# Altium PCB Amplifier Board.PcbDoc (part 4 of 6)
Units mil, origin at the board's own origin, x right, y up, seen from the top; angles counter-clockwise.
Board outline 6000 x 2640 mil, 6 copper layers (Top Layer, GND, VCC, BASES, GND (Plane3), Bottom Layer), stack 63.9 mil thick; 884 components, 484 nets, 2029 pads, 464 vias.
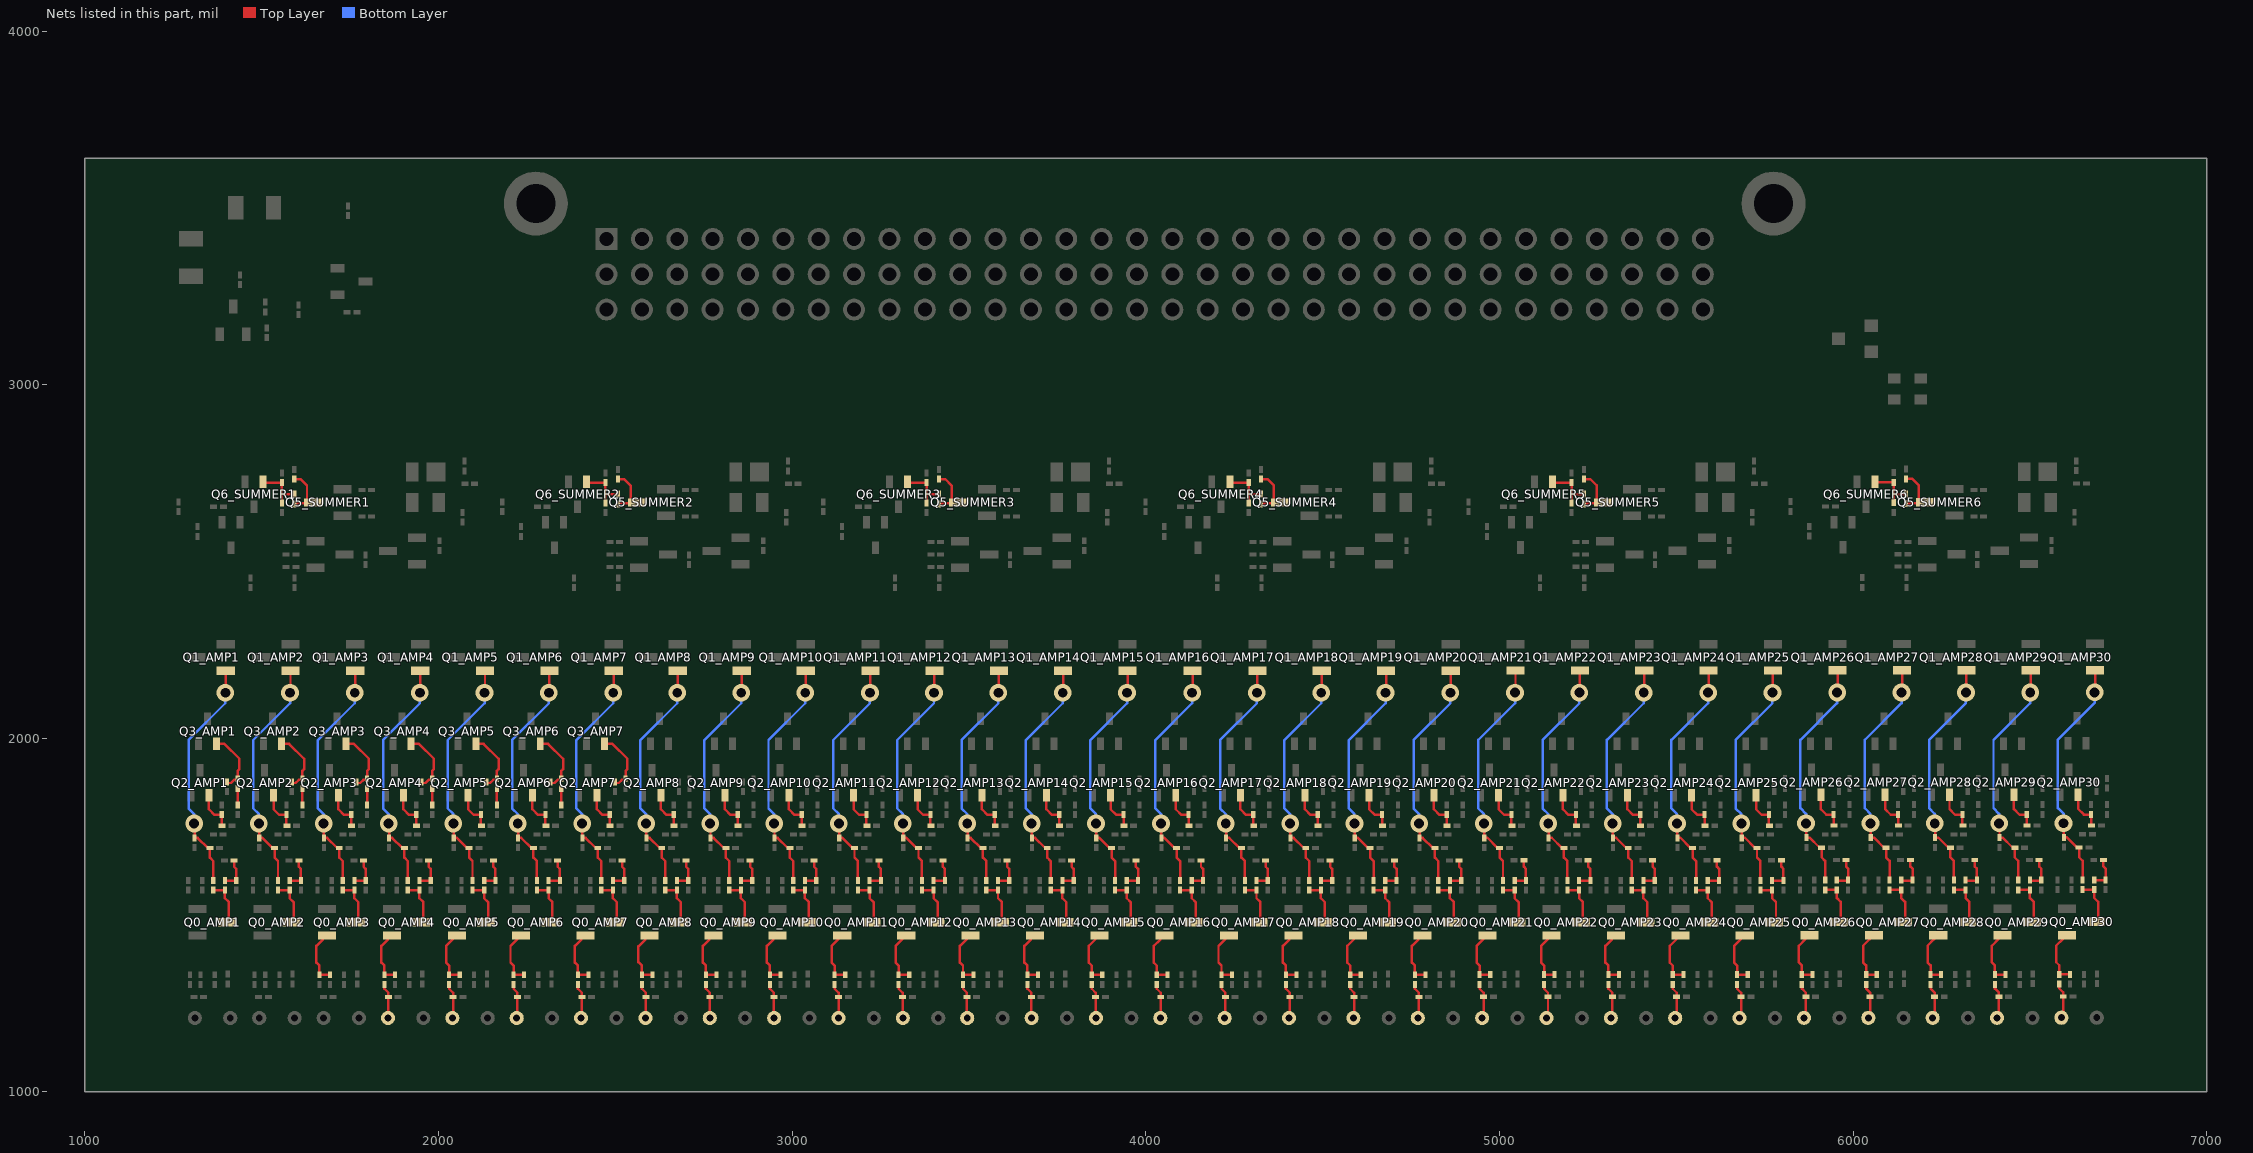
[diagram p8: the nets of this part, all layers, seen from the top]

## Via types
v1: diameter 50, hole 28, Top Layer to Bottom Layer, 433 vias
v2: diameter 50, hole 28, Top Layer to Bottom Layer, tented top, 31 vias

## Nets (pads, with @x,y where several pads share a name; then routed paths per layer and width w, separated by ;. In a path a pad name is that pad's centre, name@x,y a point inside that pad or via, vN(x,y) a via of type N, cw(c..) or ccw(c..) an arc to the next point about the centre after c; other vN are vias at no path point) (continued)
NetC2_AMP3_2: C2_AMP3.2 Q0_AMP3.2 R1_AMP3.2 | length 152.2
  Top Layer w7: Q0_AMP3.2@1673,1442.6 1673,1431.56 1654.5,1413.06 1654.5,1365.93 1663,1357.43 C2_AMP3.2@1663,1331.56 R1_AMP3.2@1693,1331.56
NetC2_AMP4_1: C2_AMP4.1 R19_AMP4.2 SIPM_AMP4.1 | length 98.4
  Top Layer w7: C2_AMP4.1@1847,1304 1847,1291.88 1858.22,1280.66 R19_AMP4.2@1858.22,1269 SIPM_AMP4.1@1858.22,1210.22
NetC2_AMP4_2: C2_AMP4.2 Q0_AMP4.2 R1_AMP4.2 | length 152.2
  Top Layer w7: Q0_AMP4.2@1857,1442.6 1857,1431.56 1838.5,1413.06 1838.5,1365.93 1847,1357.43 C2_AMP4.2@1847,1331.56 R1_AMP4.2@1877,1331.56
NetC2_AMP5_1: C2_AMP5.1 R19_AMP5.2 SIPM_AMP5.1 | length 98.4
  Top Layer w7: C2_AMP5.1@2030,1304 2030,1291.88 2041.22,1280.66 R19_AMP5.2@2041.22,1269 SIPM_AMP5.1@2041.22,1210.22
NetC2_AMP5_2: C2_AMP5.2 Q0_AMP5.2 R1_AMP5.2 | length 152.2
  Top Layer w7: Q0_AMP5.2@2040,1442.6 2040,1431.56 2021.5,1413.06 2021.5,1365.93 2030,1357.43 C2_AMP5.2@2030,1331.56 R1_AMP5.2@2060,1331.56
NetC2_AMP6_1: C2_AMP6.1 R19_AMP6.2 SIPM_AMP6.1 | length 98.4
  Top Layer w7: C2_AMP6.1@2212,1304 2212,1291.88 2223.22,1280.66 R19_AMP6.2@2223.22,1269 SIPM_AMP6.1@2223.22,1210.22
NetC2_AMP6_2: C2_AMP6.2 Q0_AMP6.2 R1_AMP6.2 | length 152.2
  Top Layer w7: Q0_AMP6.2@2222,1442.6 2222,1431.56 2203.5,1413.06 2203.5,1365.93 2212,1357.43 C2_AMP6.2@2212,1331.56 R1_AMP6.2@2242,1331.56
NetC2_AMP7_1: C2_AMP7.1 R19_AMP7.2 SIPM_AMP7.1 | length 98.4
  Top Layer w7: C2_AMP7.1@2394,1304 2394,1291.88 2405.22,1280.66 R19_AMP7.2@2405.22,1269 SIPM_AMP7.1@2405.22,1210.22
NetC2_AMP7_2: C2_AMP7.2 Q0_AMP7.2 R1_AMP7.2 | length 152.2
  Top Layer w7: Q0_AMP7.2@2404,1442.6 2404,1431.56 2385.5,1413.06 2385.5,1365.93 2394,1357.43 C2_AMP7.2@2394,1331.56 R1_AMP7.2@2424,1331.56
NetC2_AMP8_1: C2_AMP8.1 R19_AMP8.2 SIPM_AMP8.1 | length 98.4
  Top Layer w7: C2_AMP8.1@2575,1304 2575,1291.88 2586.22,1280.66 R19_AMP8.2@2586.22,1269 SIPM_AMP8.1@2586.22,1210.22
NetC2_AMP8_2: C2_AMP8.2 Q0_AMP8.2 R1_AMP8.2 | length 153.5
  Top Layer w7: Q0_AMP8.2@2585,1442.6 2585,1431.56 2565,1411.56 2565,1367.43 2575,1357.43 C2_AMP8.2@2575,1331.56 R1_AMP8.2@2605,1331.56
NetC2_AMP9_1: C2_AMP9.1 R19_AMP9.2 SIPM_AMP9.1 | length 98.4
  Top Layer w7: C2_AMP9.1@2756,1304 2756,1291.88 2767.22,1280.66 R19_AMP9.2@2767.22,1269 SIPM_AMP9.1@2767.22,1210.22
NetC2_AMP9_2: C2_AMP9.2 Q0_AMP9.2 R1_AMP9.2 | length 152.2
  Top Layer w7: Q0_AMP9.2@2766,1442.6 2766,1431.56 2747.5,1413.06 2747.5,1365.93 2756,1357.43 C2_AMP9.2@2756,1331.56 R1_AMP9.2@2786,1331.56
NetC2_AMP10_1: C2_AMP10.1 R19_AMP10.2 SIPM_AMP10.1 | length 98.4
  Top Layer w7: C2_AMP10.1@2937,1304 2937,1291.88 2948.22,1280.66 R19_AMP10.2@2948.22,1269 SIPM_AMP10.1@2948.22,1210.22
NetC2_AMP10_2: C2_AMP10.2 Q0_AMP10.2 R1_AMP10.2 | length 152.2
  Top Layer w7: Q0_AMP10.2@2947,1442.6 2947,1431.56 2928.5,1413.06 2928.5,1365.93 2937,1357.43 C2_AMP10.2@2937,1331.56 R1_AMP10.2@2967,1331.56
NetC2_AMP11_1: C2_AMP11.1 R19_AMP11.2 SIPM_AMP11.1 | length 98.4
  Top Layer w7: C2_AMP11.1@3120,1304 3120,1291.88 3131.22,1280.66 R19_AMP11.2@3131.22,1269 SIPM_AMP11.1@3131.22,1210.22
NetC2_AMP11_2: C2_AMP11.2 Q0_AMP11.2 R1_AMP11.2 | length 152.2
  Top Layer w7: Q0_AMP11.2@3130,1442.6 3130,1431.56 3111.5,1413.06 3111.5,1365.93 3120,1357.43 C2_AMP11.2@3120,1331.56 R1_AMP11.2@3150,1331.56
NetC2_AMP12_1: C2_AMP12.1 R19_AMP12.2 SIPM_AMP12.1 | length 98.4
  Top Layer w7: C2_AMP12.1@3301,1304 3301,1291.88 3312.22,1280.66 R19_AMP12.2@3312.22,1269 SIPM_AMP12.1@3312.22,1210.22
NetC2_AMP12_2: C2_AMP12.2 Q0_AMP12.2 R1_AMP12.2 | length 152.2
  Top Layer w7: Q0_AMP12.2@3311,1442.6 3311,1431.56 3292.5,1413.06 3292.5,1365.93 3301,1357.43 C2_AMP12.2@3301,1331.56 R1_AMP12.2@3331,1331.56
NetC2_AMP13_1: C2_AMP13.1 R19_AMP13.2 SIPM_AMP13.1 | length 98.4
  Top Layer w7: C2_AMP13.1@3483,1304 3483,1291.88 3494.22,1280.66 R19_AMP13.2@3494.22,1269 SIPM_AMP13.1@3494.22,1210.22
NetC2_AMP13_2: C2_AMP13.2 Q0_AMP13.2 R1_AMP13.2 | length 152.2
  Top Layer w7: Q0_AMP13.2@3493,1442.6 3493,1431.56 3474.5,1413.06 3474.5,1365.93 3483,1357.43 C2_AMP13.2@3483,1331.56 R1_AMP13.2@3513,1331.56
NetC2_AMP14_1: C2_AMP14.1 R19_AMP14.2 SIPM_AMP14.1 | length 98.4
  Top Layer w7: C2_AMP14.1@3665,1304 3665,1291.88 3676.22,1280.66 R19_AMP14.2@3676.22,1269 SIPM_AMP14.1@3676.22,1210.22
NetC2_AMP14_2: C2_AMP14.2 Q0_AMP14.2 R1_AMP14.2 | length 152.2
  Top Layer w7: Q0_AMP14.2@3675,1442.6 3675,1431.56 3656.5,1413.06 3656.5,1365.93 3665,1357.43 C2_AMP14.2@3665,1331.56 R1_AMP14.2@3695,1331.56
NetC2_AMP15_1: C2_AMP15.1 R19_AMP15.2 SIPM_AMP15.1 | length 98.4
  Top Layer w7: C2_AMP15.1@3847,1304 3847,1291.88 3858.22,1280.66 R19_AMP15.2@3858.22,1269 SIPM_AMP15.1@3858.22,1210.22
NetC2_AMP15_2: C2_AMP15.2 Q0_AMP15.2 R1_AMP15.2 | length 152.2
  Top Layer w7: Q0_AMP15.2@3857,1442.6 3857,1431.56 3838.5,1413.06 3838.5,1365.93 3847,1357.43 C2_AMP15.2@3847,1331.56 R1_AMP15.2@3877,1331.56
NetC2_AMP16_1: C2_AMP16.1 R19_AMP16.2 SIPM_AMP16.1 | length 98.4
  Top Layer w7: C2_AMP16.1@4031,1304 4031,1291.88 4042.22,1280.66 R19_AMP16.2@4042.22,1269 SIPM_AMP16.1@4042.22,1210.22
NetC2_AMP16_2: C2_AMP16.2 Q0_AMP16.2 R1_AMP16.2 | length 152.2
  Top Layer w7: Q0_AMP16.2@4041,1442.6 4041,1431.56 4022.5,1413.06 4022.5,1365.93 4031,1357.43 C2_AMP16.2@4031,1331.56 R1_AMP16.2@4061,1331.56
NetC2_AMP17_1: C2_AMP17.1 R19_AMP17.2 SIPM_AMP17.1 | length 98.4
  Top Layer w7: C2_AMP17.1@4214,1304 4214,1291.88 4225.22,1280.66 R19_AMP17.2@4225.22,1269 SIPM_AMP17.1@4225.22,1210.22
NetC2_AMP17_2: C2_AMP17.2 Q0_AMP17.2 R1_AMP17.2 | length 152.2
  Top Layer w7: Q0_AMP17.2@4224,1442.6 4224,1431.56 4205.5,1413.06 4205.5,1365.93 4214,1357.43 C2_AMP17.2@4214,1331.56 R1_AMP17.2@4244,1331.56
NetC2_AMP18_1: C2_AMP18.1 R19_AMP18.2 SIPM_AMP18.1 | length 98.4
  Top Layer w7: C2_AMP18.1@4396,1304 4396,1291.88 4407.22,1280.66 R19_AMP18.2@4407.22,1269 SIPM_AMP18.1@4407.22,1210.22
NetC2_AMP18_2: C2_AMP18.2 Q0_AMP18.2 R1_AMP18.2 | length 152.2
  Top Layer w7: Q0_AMP18.2@4406,1442.6 4406,1431.56 4387.5,1413.06 4387.5,1365.93 4396,1357.43 C2_AMP18.2@4396,1331.56 R1_AMP18.2@4426,1331.56
NetC2_AMP19_1: C2_AMP19.1 R19_AMP19.2 SIPM_AMP19.1 | length 98.4
  Top Layer w7: C2_AMP19.1@4578,1304 4578,1291.88 4589.22,1280.66 R19_AMP19.2@4589.22,1269 SIPM_AMP19.1@4589.22,1210.22
NetC2_AMP19_2: C2_AMP19.2 Q0_AMP19.2 R1_AMP19.2 | length 152.2
  Top Layer w7: Q0_AMP19.2@4588,1442.6 4588,1431.56 4569.5,1413.06 4569.5,1365.93 4578,1357.43 C2_AMP19.2@4578,1331.56 R1_AMP19.2@4608,1331.56
NetC2_AMP20_1: C2_AMP20.1 R19_AMP20.2 SIPM_AMP20.1 | length 98.4
  Top Layer w7: C2_AMP20.1@4761,1304 4761,1291.88 4772.22,1280.66 R19_AMP20.2@4772.22,1269 SIPM_AMP20.1@4772.22,1210.22
NetC2_AMP20_2: C2_AMP20.2 Q0_AMP20.2 R1_AMP20.2 | length 152.2
  Top Layer w7: Q0_AMP20.2@4771,1442.6 4771,1431.56 4752.5,1413.06 4752.5,1365.93 4761,1357.43 C2_AMP20.2@4761,1331.56 R1_AMP20.2@4791,1331.56
NetC2_AMP21_1: C2_AMP21.1 R19_AMP21.2 SIPM_AMP21.1 | length 98.4
  Top Layer w7: C2_AMP21.1@4944,1304.1 4944,1291.98 4955.22,1280.76 R19_AMP21.2@4955.22,1269.1 SIPM_AMP21.1@4955.22,1210.32
NetC2_AMP21_2: C2_AMP21.2 Q0_AMP21.2 R1_AMP21.2 | length 152.2
  Top Layer w7: Q0_AMP21.2@4954,1442.7 4954,1431.66 4935.5,1413.16 4935.5,1366.03 4944,1357.53 C2_AMP21.2@4944,1331.66 R1_AMP21.2@4974,1331.66
NetC2_AMP22_1: C2_AMP22.1 R19_AMP22.2 SIPM_AMP22.1 | length 98.4
  Top Layer w7: C2_AMP22.1@5126,1304.1 5126,1291.98 5137.22,1280.76 R19_AMP22.2@5137.22,1269.1 SIPM_AMP22.1@5137.22,1210.32
NetC2_AMP22_2: C2_AMP22.2 Q0_AMP22.2 R1_AMP22.2 | length 152.2
  Top Layer w7: Q0_AMP22.2@5136,1442.7 5136,1431.66 5117.5,1413.16 5117.5,1366.03 5126,1357.53 C2_AMP22.2@5126,1331.66 R1_AMP22.2@5156,1331.66
NetC2_AMP23_1: C2_AMP23.1 R19_AMP23.2 SIPM_AMP23.1 | length 98.4
  Top Layer w7: C2_AMP23.1@5308,1304.1 5308,1291.98 5319.22,1280.76 R19_AMP23.2@5319.22,1269.1 SIPM_AMP23.1@5319.22,1210.32
NetC2_AMP23_2: C2_AMP23.2 Q0_AMP23.2 R1_AMP23.2 | length 152.2
  Top Layer w7: Q0_AMP23.2@5318,1442.7 5318,1431.66 5299.5,1413.16 5299.5,1366.03 5308,1357.53 C2_AMP23.2@5308,1331.66 R1_AMP23.2@5338,1331.66
NetC2_AMP24_1: C2_AMP24.1 R19_AMP24.2 SIPM_AMP24.1 | length 98.4
  Top Layer w7: C2_AMP24.1@5490,1304.1 5490,1291.98 5501.22,1280.76 R19_AMP24.2@5501.22,1269.1 SIPM_AMP24.1@5501.22,1210.32
NetC2_AMP24_2: C2_AMP24.2 Q0_AMP24.2 R1_AMP24.2 | length 152.2
  Top Layer w7: Q0_AMP24.2@5500,1442.7 5500,1431.66 5481.5,1413.16 5481.5,1366.03 5490,1357.53 C2_AMP24.2@5490,1331.66 R1_AMP24.2@5520,1331.66
NetC2_AMP25_1: C2_AMP25.1 R19_AMP25.2 SIPM_AMP25.1 | length 98.4
  Top Layer w7: C2_AMP25.1@5672,1304.1 5672,1291.98 5683.22,1280.76 R19_AMP25.2@5683.22,1269.1 SIPM_AMP25.1@5683.22,1210.32
NetC2_AMP25_2: C2_AMP25.2 Q0_AMP25.2 R1_AMP25.2 | length 152.2
  Top Layer w7: Q0_AMP25.2@5682,1442.7 5682,1431.66 5663.5,1413.16 5663.5,1366.03 5672,1357.53 C2_AMP25.2@5672,1331.66 R1_AMP25.2@5702,1331.66
NetC2_AMP26_1: C2_AMP26.1 R19_AMP26.2 SIPM_AMP26.1 | length 98.4
  Top Layer w7: C2_AMP26.1@5855,1304.57 5855,1292.45 5866.22,1281.23 R19_AMP26.2@5866.22,1269.57 SIPM_AMP26.1@5866.22,1210.79
NetC2_AMP26_2: C2_AMP26.2 Q0_AMP26.2 R1_AMP26.2 | length 152.2
  Top Layer w7: Q0_AMP26.2@5865,1443.17 5865,1432.13 5846.5,1413.63 5846.5,1366.5 5855,1358 C2_AMP26.2@5855,1332.13 R1_AMP26.2@5885,1332.13
NetC2_AMP27_1: C2_AMP27.1 R19_AMP27.2 SIPM_AMP27.1 | length 98.4
  Top Layer w7: C2_AMP27.1@6037,1304.57 6037,1292.45 6048.22,1281.23 R19_AMP27.2@6048.22,1269.57 SIPM_AMP27.1@6048.22,1210.79
NetC2_AMP27_2: C2_AMP27.2 Q0_AMP27.2 R1_AMP27.2 | length 152.2
  Top Layer w7: Q0_AMP27.2@6047,1443.17 6047,1432.13 6028.5,1413.63 6028.5,1366.5 6037,1358 C2_AMP27.2@6037,1332.13 R1_AMP27.2@6067,1332.13
NetC2_AMP28_1: C2_AMP28.1 R19_AMP28.2 SIPM_AMP28.1 | length 98.4
  Top Layer w7: C2_AMP28.1@6219,1304.57 6219,1292.45 6230.22,1281.23 R19_AMP28.2@6230.22,1269.57 SIPM_AMP28.1@6230.22,1210.79
NetC2_AMP28_2: C2_AMP28.2 Q0_AMP28.2 R1_AMP28.2 | length 152.2
  Top Layer w7: Q0_AMP28.2@6229,1443.17 6229,1432.13 6210.5,1413.63 6210.5,1366.5 6219,1358 C2_AMP28.2@6219,1332.13 R1_AMP28.2@6249,1332.13
NetC2_AMP29_1: C2_AMP29.1 R19_AMP29.2 SIPM_AMP29.1 | length 98.4
  Top Layer w7: C2_AMP29.1@6401,1304.57 6401,1292.45 6412.22,1281.23 R19_AMP29.2@6412.22,1269.57 SIPM_AMP29.1@6412.22,1210.79
NetC2_AMP29_2: C2_AMP29.2 Q0_AMP29.2 R1_AMP29.2 | length 152.2
  Top Layer w7: Q0_AMP29.2@6411,1443.17 6411,1432.13 6392.5,1413.63 6392.5,1366.5 6401,1358 C2_AMP29.2@6401,1332.13 R1_AMP29.2@6431,1332.13
NetC2_AMP30_1: C2_AMP30.1 R19_AMP30.2 SIPM_AMP30.1 | length 98.4
  Top Layer w7: C2_AMP30.1@6583,1305 6583,1292.88 6594.22,1281.66 R19_AMP30.2@6594.22,1270 SIPM_AMP30.1@6594.22,1211.22
NetC2_AMP30_2: C2_AMP30.2 Q0_AMP30.2 R1_AMP30.2 | length 152.2
  Top Layer w7: Q0_AMP30.2@6593,1443.6 6593,1432.56 6574.5,1414.06 6574.5,1366.93 6583,1358.43 C2_AMP30.2@6583,1332.56 R1_AMP30.2@6613,1332.56
NetC3_AMP1_2: C3_AMP1.2 R6_AMP1.2 R20_AMP1.1 | length 84.4
  Top Layer w7: R6_AMP1.2@1396,1597.18 1421.5,1597.18 ; R20_AMP1.1@1422,1655 1422,1637 1428,1631 C3_AMP1.2@1428,1598.56
NetC3_AMP2_2: C3_AMP2.2 R6_AMP2.2 R20_AMP2.1 | length 84.4
  Top Layer w7: R6_AMP2.2@1579,1597.18 1604.5,1597.18 ; R20_AMP2.1@1605,1655 1605,1637 1611,1631 C3_AMP2.2@1611,1598.56
NetC3_AMP3_2: C3_AMP3.2 R6_AMP3.2 R20_AMP3.1 | length 84.4
  Top Layer w7: R6_AMP3.2@1762,1597.18 1787.5,1597.18 ; R20_AMP3.1@1788,1655 1788,1637 1794,1631 C3_AMP3.2@1794,1598.56
NetC3_AMP4_2: C3_AMP4.2 R6_AMP4.2 R20_AMP4.1 | length 84.4
  Top Layer w7: R6_AMP4.2@1946,1597.18 1971.5,1597.18 ; R20_AMP4.1@1972,1655 1972,1637 1978,1631 C3_AMP4.2@1978,1598.56
NetC3_AMP5_2: C3_AMP5.2 R6_AMP5.2 R20_AMP5.1 | length 84.4
  Top Layer w7: R6_AMP5.2@2129,1597.18 2154.5,1597.18 ; R20_AMP5.1@2155,1655 2155,1637 2161,1631 C3_AMP5.2@2161,1598.56
NetC3_AMP6_2: C3_AMP6.2 R6_AMP6.2 R20_AMP6.1 | length 84.4
  Top Layer w7: R6_AMP6.2@2311,1597.18 2336.5,1597.18 ; R20_AMP6.1@2337,1655 2337,1637 2343,1631 C3_AMP6.2@2343,1598.56
NetC3_AMP7_2: C3_AMP7.2 R6_AMP7.2 R20_AMP7.1 | length 84.4
  Top Layer w7: R6_AMP7.2@2493,1597.18 2518.5,1597.18 ; R20_AMP7.1@2519,1655 2519,1637 2525,1631 C3_AMP7.2@2525,1598.56
NetC3_AMP8_2: C3_AMP8.2 R6_AMP8.2 R20_AMP8.1 | length 84.4
  Top Layer w7: R6_AMP8.2@2674,1597.18 2699.5,1597.18 ; R20_AMP8.1@2700,1655 2700,1637 2706,1631 C3_AMP8.2@2706,1598.56
NetC3_AMP9_2: C3_AMP9.2 R6_AMP9.2 R20_AMP9.1 | length 84.4
  Top Layer w7: R6_AMP9.2@2855,1597.18 2880.5,1597.18 ; R20_AMP9.1@2881,1655 2881,1637 2887,1631 C3_AMP9.2@2887,1598.56
NetC3_AMP10_2: C3_AMP10.2 R6_AMP10.2 R20_AMP10.1 | length 84.4
  Top Layer w7: R6_AMP10.2@3036,1597.18 3061.5,1597.18 ; R20_AMP10.1@3062,1655 3062,1637 3068,1631 C3_AMP10.2@3068,1598.56
NetC3_AMP11_2: C3_AMP11.2 R6_AMP11.2 R20_AMP11.1 | length 84.4
  Top Layer w7: R6_AMP11.2@3219,1597.18 3244.5,1597.18 ; R20_AMP11.1@3245,1655 3245,1637 3251,1631 C3_AMP11.2@3251,1598.56
NetC3_AMP12_2: C3_AMP12.2 R6_AMP12.2 R20_AMP12.1 | length 84.4
  Top Layer w7: R6_AMP12.2@3400,1597.18 3425.5,1597.18 ; R20_AMP12.1@3426,1655 3426,1637 3432,1631 C3_AMP12.2@3432,1598.56
NetC3_AMP13_2: C3_AMP13.2 R6_AMP13.2 R20_AMP13.1 | length 84.4
  Top Layer w7: R6_AMP13.2@3582,1597.18 3607.5,1597.18 ; R20_AMP13.1@3608,1655 3608,1637 3614,1631 C3_AMP13.2@3614,1598.56
NetC3_AMP14_2: C3_AMP14.2 R6_AMP14.2 R20_AMP14.1 | length 84.4
  Top Layer w7: R6_AMP14.2@3764,1597.18 3789.5,1597.18 ; R20_AMP14.1@3790,1655 3790,1637 3796,1631 C3_AMP14.2@3796,1598.56
NetC3_AMP15_2: C3_AMP15.2 R6_AMP15.2 R20_AMP15.1 | length 84.4
  Top Layer w7: R6_AMP15.2@3946,1597.18 3971.5,1597.18 ; R20_AMP15.1@3972,1655 3972,1637 3978,1631 C3_AMP15.2@3978,1598.56
NetC3_AMP16_2: C3_AMP16.2 R6_AMP16.2 R20_AMP16.1 | length 84.4
  Top Layer w7: R6_AMP16.2@4130,1597.18 4155.5,1597.18 ; R20_AMP16.1@4156,1655 4156,1637 4162,1631 C3_AMP16.2@4162,1598.56
NetC3_AMP17_2: C3_AMP17.2 R6_AMP17.2 R20_AMP17.1 | length 84.4
  Top Layer w7: R6_AMP17.2@4313,1597.18 4338.5,1597.18 ; R20_AMP17.1@4339,1655 4339,1637 4345,1631 C3_AMP17.2@4345,1598.56
NetC3_AMP18_2: C3_AMP18.2 R6_AMP18.2 R20_AMP18.1 | length 84.4
  Top Layer w7: R6_AMP18.2@4495,1597.18 4520.5,1597.18 ; R20_AMP18.1@4521,1655 4521,1637 4527,1631 C3_AMP18.2@4527,1598.56
NetC3_AMP19_2: C3_AMP19.2 R6_AMP19.2 R20_AMP19.1 | length 84.4
  Top Layer w7: R6_AMP19.2@4677,1597.18 4702.5,1597.18 ; R20_AMP19.1@4703,1655 4703,1637 4709,1631 C3_AMP19.2@4709,1598.56
NetC3_AMP20_2: C3_AMP20.2 R6_AMP20.2 R20_AMP20.1 | length 84.4
  Top Layer w7: R6_AMP20.2@4860,1597.18 4885.5,1597.18 ; R20_AMP20.1@4886,1655 4886,1637 4892,1631 C3_AMP20.2@4892,1598.56
NetC3_AMP21_2: C3_AMP21.2 R6_AMP21.2 R20_AMP21.1 | length 84.4
  Top Layer w7: R6_AMP21.2@5043,1597.28 5068.5,1597.28 ; R20_AMP21.1@5069,1655.1 5069,1637.1 5075,1631.1 C3_AMP21.2@5075,1598.66
NetC3_AMP22_2: C3_AMP22.2 R6_AMP22.2 R20_AMP22.1 | length 84.4
  Top Layer w7: R6_AMP22.2@5225,1597.28 5250.5,1597.28 ; R20_AMP22.1@5251,1655.1 5251,1637.1 5257,1631.1 C3_AMP22.2@5257,1598.66
NetC3_AMP23_2: C3_AMP23.2 R6_AMP23.2 R20_AMP23.1 | length 84.4
  Top Layer w7: R6_AMP23.2@5407,1597.28 5432.5,1597.28 ; R20_AMP23.1@5433,1655.1 5433,1637.1 5439,1631.1 C3_AMP23.2@5439,1598.66
NetC3_AMP24_2: C3_AMP24.2 R6_AMP24.2 R20_AMP24.1 | length 84.4
  Top Layer w7: R6_AMP24.2@5589,1597.28 5614.5,1597.28 ; R20_AMP24.1@5615,1655.1 5615,1637.1 5621,1631.1 C3_AMP24.2@5621,1598.66
NetC3_AMP25_2: C3_AMP25.2 R6_AMP25.2 R20_AMP25.1 | length 84.4
  Top Layer w7: R6_AMP25.2@5771,1597.28 5796.5,1597.28 ; R20_AMP25.1@5797,1655.1 5797,1637.1 5803,1631.1 C3_AMP25.2@5803,1598.66
NetC3_AMP26_2: C3_AMP26.2 R6_AMP26.2 R20_AMP26.1 | length 84.4
  Top Layer w7: R6_AMP26.2@5954,1597.75 5979.5,1597.75 ; R20_AMP26.1@5980,1655.57 5980,1637.57 5986,1631.57 C3_AMP26.2@5986,1599.13
NetC3_AMP27_2: C3_AMP27.2 R6_AMP27.2 R20_AMP27.1 | length 84.4
  Top Layer w7: R6_AMP27.2@6136,1597.75 6161.5,1597.75 ; R20_AMP27.1@6162,1655.57 6162,1637.57 6168,1631.57 C3_AMP27.2@6168,1599.13
NetC3_AMP28_2: C3_AMP28.2 R6_AMP28.2 R20_AMP28.1 | length 84.4
  Top Layer w7: R6_AMP28.2@6318,1597.75 6343.5,1597.75 ; R20_AMP28.1@6344,1655.57 6344,1637.57 6350,1631.57 C3_AMP28.2@6350,1599.13
NetC3_AMP29_2: C3_AMP29.2 R6_AMP29.2 R20_AMP29.1 | length 84.4
  Top Layer w7: R6_AMP29.2@6500,1597.75 6525.5,1597.75 ; R20_AMP29.1@6526,1655.57 6526,1637.57 6532,1631.57 C3_AMP29.2@6532,1599.13
NetC3_AMP30_2: C3_AMP30.2 R6_AMP30.2 R20_AMP30.1 | length 84.4
  Top Layer w7: R6_AMP30.2@6682,1598.18 6707.5,1598.18 ; R20_AMP30.1@6708,1656 6708,1638 6714,1632 C3_AMP30.2@6714,1599.56
NetC4_AMP1_1: C4_AMP1.1 Q0_AMP1.3 R6_AMP1.1 | length 127.9
  Top Layer w7: C4_AMP1.1@1363,1571 R6_AMP1.1@1396,1571 ; R6_AMP1.1@1396,1572.38 R6_AMP1.1@1396,1571 ; Q0_AMP1.3@1407,1482 1407,1536.9 1396,1547.9 R6_AMP1.1@1396,1571
NetC4_AMP1_2: C4_AMP1.2 Q1_AMP1.1 R2_AMP1.1 R3_AMP1.2 | length 672.2
  Top Layer w7: v1@1310,1758 R3_AMP1.2@1310,1718.78 1318.78,1718.78 1347.56,1690 R2_AMP1.1@1353.22,1690 1353.22,1662.78 1363,1653 C4_AMP1.2@1363,1598.56 C4_AMP1.2@1363,1597.18 ; v1@1398.34,2130.34 Q1_AMP1.1@1398.34,2191.6
  Bottom Layer w7: v1(1309,1759) 1309,1786 1293,1802 1293,1995.29 1397,2099.29 v1(1397,2129)
NetC4_AMP2_1: C4_AMP2.1 Q0_AMP2.3 R6_AMP2.1 | length 127.9
  Top Layer w7: C4_AMP2.1@1546,1571 R6_AMP2.1@1579,1571 ; R6_AMP2.1@1579,1572.38 R6_AMP2.1@1579,1571 ; Q0_AMP2.3@1590,1482 1590,1536.9 1579,1547.9 R6_AMP2.1@1579,1571
NetC4_AMP2_2: C4_AMP2.2 Q1_AMP2.1 R2_AMP2.1 R3_AMP2.2 | length 672.2
  Top Layer w7: v1@1493,1758 R3_AMP2.2@1493,1718.78 1501.78,1718.78 1530.56,1690 R2_AMP2.1@1536.22,1690 1536.22,1662.78 1546,1653 C4_AMP2.2@1546,1598.56 C4_AMP2.2@1546,1597.18 ; v1@1581.34,2130.34 Q1_AMP2.1@1581.34,2191.6
  Bottom Layer w7: v1(1492,1759) 1492,1786 1476,1802 1476,1995.29 1580,2099.29 v1(1580,2129)
NetC4_AMP3_1: C4_AMP3.1 Q0_AMP3.3 R6_AMP3.1 | length 127.9
  Top Layer w7: C4_AMP3.1@1729,1571 R6_AMP3.1@1762,1571 ; R6_AMP3.1@1762,1572.38 R6_AMP3.1@1762,1571 ; Q0_AMP3.3@1773,1482 1773,1536.9 1762,1547.9 R6_AMP3.1@1762,1571
NetC4_AMP3_2: C4_AMP3.2 Q1_AMP3.1 R2_AMP3.1 R3_AMP3.2 | length 672.2
  Top Layer w7: v1@1676,1758 R3_AMP3.2@1676,1718.78 1684.78,1718.78 1713.56,1690 R2_AMP3.1@1719.22,1690 1719.22,1662.78 1729,1653 C4_AMP3.2@1729,1598.56 C4_AMP3.2@1729,1597.18 ; v1@1764.34,2130.34 Q1_AMP3.1@1764.34,2191.6
  Bottom Layer w7: v1(1675,1759) 1675,1786 1659,1802 1659,1995.29 1763,2099.29 v1(1763,2129)
NetC4_AMP4_1: C4_AMP4.1 Q0_AMP4.3 R6_AMP4.1 | length 127.9
  Top Layer w7: C4_AMP4.1@1913,1571 R6_AMP4.1@1946,1571 ; R6_AMP4.1@1946,1572.38 R6_AMP4.1@1946,1571 ; Q0_AMP4.3@1957,1482 1957,1536.9 1946,1547.9 R6_AMP4.1@1946,1571
NetC4_AMP4_2: C4_AMP4.2 Q1_AMP4.1 R2_AMP4.1 R3_AMP4.2 | length 672.2
  Top Layer w7: v1@1860,1758 R3_AMP4.2@1860,1718.78 1868.78,1718.78 1897.56,1690 R2_AMP4.1@1903.22,1690 1903.22,1662.78 1913,1653 C4_AMP4.2@1913,1598.56 C4_AMP4.2@1913,1597.18 ; v1@1948.34,2130.34 Q1_AMP4.1@1948.34,2191.6
  Bottom Layer w7: v1(1859,1759) 1859,1786 1843,1802 1843,1995.29 1947,2099.29 v1(1947,2129)
NetC4_AMP5_1: C4_AMP5.1 Q0_AMP5.3 R6_AMP5.1 | length 127.9
  Top Layer w7: C4_AMP5.1@2096,1571 R6_AMP5.1@2129,1571 ; R6_AMP5.1@2129,1572.38 R6_AMP5.1@2129,1571 ; Q0_AMP5.3@2140,1482 2140,1536.9 2129,1547.9 R6_AMP5.1@2129,1571
NetC4_AMP5_2: C4_AMP5.2 Q1_AMP5.1 R2_AMP5.1 R3_AMP5.2 | length 672.2
  Top Layer w7: v1@2043,1758 R3_AMP5.2@2043,1718.78 2051.78,1718.78 2080.56,1690 R2_AMP5.1@2086.22,1690 2086.22,1662.78 2096,1653 C4_AMP5.2@2096,1598.56 C4_AMP5.2@2096,1597.18 ; v1@2131.34,2130.34 Q1_AMP5.1@2131.34,2191.6
  Bottom Layer w7: v1(2042,1759) 2042,1786 2026,1802 2026,1995.29 2130,2099.29 v1(2130,2129)
NetC4_AMP6_1: C4_AMP6.1 Q0_AMP6.3 R6_AMP6.1 | length 127.9
  Top Layer w7: C4_AMP6.1@2278,1571 R6_AMP6.1@2311,1571 ; R6_AMP6.1@2311,1572.38 R6_AMP6.1@2311,1571 ; Q0_AMP6.3@2322,1482 2322,1536.9 2311,1547.9 R6_AMP6.1@2311,1571
NetC4_AMP6_2: C4_AMP6.2 Q1_AMP6.1 R2_AMP6.1 R3_AMP6.2 | length 672.2
  Top Layer w7: v1@2225,1758 R3_AMP6.2@2225,1718.78 2233.78,1718.78 2262.56,1690 R2_AMP6.1@2268.22,1690 2268.22,1662.78 2278,1653 C4_AMP6.2@2278,1598.56 C4_AMP6.2@2278,1597.18 ; v1@2313.34,2130.34 Q1_AMP6.1@2313.34,2191.6
  Bottom Layer w7: v1(2224,1759) 2224,1786 2208,1802 2208,1995.29 2312,2099.29 v1(2312,2129)
NetC4_AMP7_1: C4_AMP7.1 Q0_AMP7.3 R6_AMP7.1 | length 127.9
  Top Layer w7: C4_AMP7.1@2460,1571 R6_AMP7.1@2493,1571 ; R6_AMP7.1@2493,1572.38 R6_AMP7.1@2493,1571 ; Q0_AMP7.3@2504,1482 2504,1536.9 2493,1547.9 R6_AMP7.1@2493,1571
NetC4_AMP7_2: C4_AMP7.2 Q1_AMP7.1 R2_AMP7.1 R3_AMP7.2 | length 672.2
  Top Layer w7: v1@2407,1758 R3_AMP7.2@2407,1718.78 2415.78,1718.78 2444.56,1690 R2_AMP7.1@2450.22,1690 2450.22,1662.78 2460,1653 C4_AMP7.2@2460,1598.56 C4_AMP7.2@2460,1597.18 ; v1@2495.34,2130.34 Q1_AMP7.1@2495.34,2191.6
  Bottom Layer w7: v1(2406,1759) 2406,1786 2390,1802 2390,1995.29 2494,2099.29 v1(2494,2129)
NetC4_AMP8_1: C4_AMP8.1 Q0_AMP8.3 R6_AMP8.1 | length 127.9
  Top Layer w7: C4_AMP8.1@2641,1571 R6_AMP8.1@2674,1571 ; R6_AMP8.1@2674,1572.38 R6_AMP8.1@2674,1571 ; Q0_AMP8.3@2685,1482 2685,1536.9 2674,1547.9 R6_AMP8.1@2674,1571
NetC4_AMP8_2: C4_AMP8.2 Q1_AMP8.1 R2_AMP8.1 R3_AMP8.2 | length 672.2
  Top Layer w7: v1@2588,1758 R3_AMP8.2@2588,1718.78 2596.78,1718.78 2625.56,1690 R2_AMP8.1@2631.22,1690 2631.22,1662.78 2641,1653 C4_AMP8.2@2641,1598.56 C4_AMP8.2@2641,1597.18 ; v1@2676.34,2130.34 Q1_AMP8.1@2676.34,2191.6
  Bottom Layer w7: v1(2587,1759) 2587,1786 2571,1802 2571,1995.29 2675,2099.29 v1(2675,2129)
NetC4_AMP9_1: C4_AMP9.1 Q0_AMP9.3 R6_AMP9.1 | length 127.9
  Top Layer w7: C4_AMP9.1@2822,1571 R6_AMP9.1@2855,1571 ; R6_AMP9.1@2855,1572.38 R6_AMP9.1@2855,1571 ; Q0_AMP9.3@2866,1482 2866,1536.9 2855,1547.9 R6_AMP9.1@2855,1571
NetC4_AMP9_2: C4_AMP9.2 Q1_AMP9.1 R2_AMP9.1 R3_AMP9.2 | length 672.2
  Top Layer w7: v1@2769,1758 R3_AMP9.2@2769,1718.78 2777.78,1718.78 2806.56,1690 R2_AMP9.1@2812.22,1690 2812.22,1662.78 2822,1653 C4_AMP9.2@2822,1598.56 C4_AMP9.2@2822,1597.18 ; v1@2857.34,2130.34 Q1_AMP9.1@2857.34,2191.6
  Bottom Layer w7: v1(2768,1759) 2768,1786 2752,1802 2752,1995.29 2856,2099.29 v1(2856,2129)
NetC4_AMP10_1: C4_AMP10.1 Q0_AMP10.3 R6_AMP10.1 | length 127.9
  Top Layer w7: C4_AMP10.1@3003,1571 R6_AMP10.1@3036,1571 ; R6_AMP10.1@3036,1572.38 R6_AMP10.1@3036,1571 ; Q0_AMP10.3@3047,1482 3047,1536.9 3036,1547.9 R6_AMP10.1@3036,1571
NetC4_AMP10_2: C4_AMP10.2 Q1_AMP10.1 R2_AMP10.1 R3_AMP10.2 | length 672.2
  Top Layer w7: v1@2950,1758 R3_AMP10.2@2950,1718.78 2958.78,1718.78 2987.56,1690 R2_AMP10.1@2993.22,1690 2993.22,1662.78 3003,1653 C4_AMP10.2@3003,1598.56 C4_AMP10.2@3003,1597.18 ; v1@3038.34,2130.34 Q1_AMP10.1@3038.34,2191.6
  Bottom Layer w7: v1(2949,1759) 2949,1786 2933,1802 2933,1995.29 3037,2099.29 v1(3037,2129)
NetC4_AMP11_1: C4_AMP11.1 Q0_AMP11.3 R6_AMP11.1 | length 127.9
  Top Layer w7: C4_AMP11.1@3186,1571 R6_AMP11.1@3219,1571 ; R6_AMP11.1@3219,1572.38 R6_AMP11.1@3219,1571 ; Q0_AMP11.3@3230,1482 3230,1536.9 3219,1547.9 R6_AMP11.1@3219,1571
NetC4_AMP11_2: C4_AMP11.2 Q1_AMP11.1 R2_AMP11.1 R3_AMP11.2 | length 672.2
  Top Layer w7: v1@3133,1758 R3_AMP11.2@3133,1718.78 3141.78,1718.78 3170.56,1690 R2_AMP11.1@3176.22,1690 3176.22,1662.78 3186,1653 C4_AMP11.2@3186,1598.56 C4_AMP11.2@3186,1597.18 ; v1@3221.34,2130.34 Q1_AMP11.1@3221.34,2191.6
  Bottom Layer w7: v1(3132,1759) 3132,1786 3116,1802 3116,1995.29 3220,2099.29 v1(3220,2129)
NetC4_AMP12_1: C4_AMP12.1 Q0_AMP12.3 R6_AMP12.1 | length 127.9
  Top Layer w7: C4_AMP12.1@3367,1571 R6_AMP12.1@3400,1571 ; R6_AMP12.1@3400,1572.38 R6_AMP12.1@3400,1571 ; Q0_AMP12.3@3411,1482 3411,1536.9 3400,1547.9 R6_AMP12.1@3400,1571
NetC4_AMP12_2: C4_AMP12.2 Q1_AMP12.1 R2_AMP12.1 R3_AMP12.2 | length 672.2
  Top Layer w7: v1@3314,1758 R3_AMP12.2@3314,1718.78 3322.78,1718.78 3351.56,1690 R2_AMP12.1@3357.22,1690 3357.22,1662.78 3367,1653 C4_AMP12.2@3367,1598.56 C4_AMP12.2@3367,1597.18 ; v1@3402.34,2130.34 Q1_AMP12.1@3402.34,2191.6
  Bottom Layer w7: v1(3313,1759) 3313,1786 3297,1802 3297,1995.29 3401,2099.29 v1(3401,2129)
NetC4_AMP13_1: C4_AMP13.1 Q0_AMP13.3 R6_AMP13.1 | length 127.9
  Top Layer w7: C4_AMP13.1@3549,1571 R6_AMP13.1@3582,1571 ; R6_AMP13.1@3582,1572.38 R6_AMP13.1@3582,1571 ; Q0_AMP13.3@3593,1482 3593,1536.9 3582,1547.9 R6_AMP13.1@3582,1571
NetC4_AMP13_2: C4_AMP13.2 Q1_AMP13.1 R2_AMP13.1 R3_AMP13.2 | length 672.2
  Top Layer w7: v1@3496,1758 R3_AMP13.2@3496,1718.78 3504.78,1718.78 3533.56,1690 R2_AMP13.1@3539.22,1690 3539.22,1662.78 3549,1653 C4_AMP13.2@3549,1598.56 C4_AMP13.2@3549,1597.18 ; v1@3584.34,2130.34 Q1_AMP13.1@3584.34,2191.6
  Bottom Layer w7: v1(3495,1759) 3495,1786 3479,1802 3479,1995.29 3583,2099.29 v1(3583,2129)
NetC4_AMP14_1: C4_AMP14.1 Q0_AMP14.3 R6_AMP14.1 | length 127.9
  Top Layer w7: C4_AMP14.1@3731,1571 R6_AMP14.1@3764,1571 ; R6_AMP14.1@3764,1572.38 R6_AMP14.1@3764,1571 ; Q0_AMP14.3@3775,1482 3775,1536.9 3764,1547.9 R6_AMP14.1@3764,1571
NetC4_AMP14_2: C4_AMP14.2 Q1_AMP14.1 R2_AMP14.1 R3_AMP14.2 | length 672.2
  Top Layer w7: v1@3678,1758 R3_AMP14.2@3678,1718.78 3686.78,1718.78 3715.56,1690 R2_AMP14.1@3721.22,1690 3721.22,1662.78 3731,1653 C4_AMP14.2@3731,1598.56 C4_AMP14.2@3731,1597.18 ; v1@3766.34,2130.34 Q1_AMP14.1@3766.34,2191.6
  Bottom Layer w7: v1(3677,1759) 3677,1786 3661,1802 3661,1995.29 3765,2099.29 v1(3765,2129)
NetC4_AMP15_1: C4_AMP15.1 Q0_AMP15.3 R6_AMP15.1 | length 127.9
  Top Layer w7: C4_AMP15.1@3913,1571 R6_AMP15.1@3946,1571 ; R6_AMP15.1@3946,1572.38 R6_AMP15.1@3946,1571 ; Q0_AMP15.3@3957,1482 3957,1536.9 3946,1547.9 R6_AMP15.1@3946,1571
NetC4_AMP15_2: C4_AMP15.2 Q1_AMP15.1 R2_AMP15.1 R3_AMP15.2 | length 672.2
  Top Layer w7: v1@3860,1758 R3_AMP15.2@3860,1718.78 3868.78,1718.78 3897.56,1690 R2_AMP15.1@3903.22,1690 3903.22,1662.78 3913,1653 C4_AMP15.2@3913,1598.56 C4_AMP15.2@3913,1597.18 ; v1@3948.34,2130.34 Q1_AMP15.1@3948.34,2191.6
  Bottom Layer w7: v1(3859,1759) 3859,1786 3843,1802 3843,1995.29 3947,2099.29 v1(3947,2129)
NetC4_AMP16_1: C4_AMP16.1 Q0_AMP16.3 R6_AMP16.1 | length 127.9
  Top Layer w7: C4_AMP16.1@4097,1571 R6_AMP16.1@4130,1571 ; R6_AMP16.1@4130,1572.38 R6_AMP16.1@4130,1571 ; Q0_AMP16.3@4141,1482 4141,1536.9 4130,1547.9 R6_AMP16.1@4130,1571
NetC4_AMP16_2: C4_AMP16.2 Q1_AMP16.1 R2_AMP16.1 R3_AMP16.2 | length 672.2
  Top Layer w7: v1@4044,1758 R3_AMP16.2@4044,1718.78 4052.78,1718.78 4081.56,1690 R2_AMP16.1@4087.22,1690 4087.22,1662.78 4097,1653 C4_AMP16.2@4097,1598.56 C4_AMP16.2@4097,1597.18 ; v1@4132.34,2130.34 Q1_AMP16.1@4132.34,2191.6
  Bottom Layer w7: v1(4043,1759) 4043,1786 4027,1802 4027,1995.29 4131,2099.29 v1(4131,2129)
NetC4_AMP17_1: C4_AMP17.1 Q0_AMP17.3 R6_AMP17.1 | length 127.9
  Top Layer w7: C4_AMP17.1@4280,1571 R6_AMP17.1@4313,1571 ; R6_AMP17.1@4313,1572.38 R6_AMP17.1@4313,1571 ; Q0_AMP17.3@4324,1482 4324,1536.9 4313,1547.9 R6_AMP17.1@4313,1571
NetC4_AMP17_2: C4_AMP17.2 Q1_AMP17.1 R2_AMP17.1 R3_AMP17.2 | length 672.2
  Top Layer w7: v1@4227,1758 R3_AMP17.2@4227,1718.78 4235.78,1718.78 4264.56,1690 R2_AMP17.1@4270.22,1690 4270.22,1662.78 4280,1653 C4_AMP17.2@4280,1598.56 C4_AMP17.2@4280,1597.18 ; v1@4315.34,2130.34 Q1_AMP17.1@4315.34,2191.6
  Bottom Layer w7: v1(4226,1759) 4226,1786 4210,1802 4210,1995.29 4314,2099.29 v1(4314,2129)
NetC4_AMP18_1: C4_AMP18.1 Q0_AMP18.3 R6_AMP18.1 | length 127.9
  Top Layer w7: C4_AMP18.1@4462,1571 R6_AMP18.1@4495,1571 ; R6_AMP18.1@4495,1572.38 R6_AMP18.1@4495,1571 ; Q0_AMP18.3@4506,1482 4506,1536.9 4495,1547.9 R6_AMP18.1@4495,1571
NetC4_AMP18_2: C4_AMP18.2 Q1_AMP18.1 R2_AMP18.1 R3_AMP18.2 | length 672.2
  Top Layer w7: v1@4409,1758 R3_AMP18.2@4409,1718.78 4417.78,1718.78 4446.56,1690 R2_AMP18.1@4452.22,1690 4452.22,1662.78 4462,1653 C4_AMP18.2@4462,1598.56 C4_AMP18.2@4462,1597.18 ; v1@4497.34,2130.34 Q1_AMP18.1@4497.34,2191.6
  Bottom Layer w7: v1(4408,1759) 4408,1786 4392,1802 4392,1995.29 4496,2099.29 v1(4496,2129)
NetC4_AMP19_1: C4_AMP19.1 Q0_AMP19.3 R6_AMP19.1 | length 127.9
  Top Layer w7: C4_AMP19.1@4644,1571 R6_AMP19.1@4677,1571 ; R6_AMP19.1@4677,1572.38 R6_AMP19.1@4677,1571 ; Q0_AMP19.3@4688,1482 4688,1536.9 4677,1547.9 R6_AMP19.1@4677,1571
NetC4_AMP19_2: C4_AMP19.2 Q1_AMP19.1 R2_AMP19.1 R3_AMP19.2 | length 672.2
  Top Layer w7: v1@4591,1758 R3_AMP19.2@4591,1718.78 4599.78,1718.78 4628.56,1690 R2_AMP19.1@4634.22,1690 4634.22,1662.78 4644,1653 C4_AMP19.2@4644,1598.56 C4_AMP19.2@4644,1597.18 ; v1@4679.34,2130.34 Q1_AMP19.1@4679.34,2191.6
  Bottom Layer w7: v1(4590,1759) 4590,1786 4574,1802 4574,1995.29 4678,2099.29 v1(4678,2129)
NetC4_AMP20_1: C4_AMP20.1 Q0_AMP20.3 R6_AMP20.1 | length 127.9
  Top Layer w7: C4_AMP20.1@4827,1571 R6_AMP20.1@4860,1571 ; R6_AMP20.1@4860,1572.38 R6_AMP20.1@4860,1571 ; Q0_AMP20.3@4871,1482 4871,1536.9 4860,1547.9 R6_AMP20.1@4860,1571
NetC4_AMP20_2: C4_AMP20.2 Q1_AMP20.1 R2_AMP20.1 R3_AMP20.2 | length 672.2
  Top Layer w7: v1@4774,1758 R3_AMP20.2@4774,1718.78 4782.78,1718.78 4811.56,1690 R2_AMP20.1@4817.22,1690 4817.22,1662.78 4827,1653 C4_AMP20.2@4827,1598.56 C4_AMP20.2@4827,1597.18 ; v1@4862.34,2130.34 Q1_AMP20.1@4862.34,2191.6
  Bottom Layer w7: v1(4773,1759) 4773,1786 4757,1802 4757,1995.29 4861,2099.29 v1(4861,2129)
NetC4_AMP21_1: C4_AMP21.1 Q0_AMP21.3 R6_AMP21.1 | length 127.9
  Top Layer w7: C4_AMP21.1@5010,1571.1 R6_AMP21.1@5043,1571.1 ; R6_AMP21.1@5043,1572.48 R6_AMP21.1@5043,1571.1 ; Q0_AMP21.3@5054,1482.1 5054,1537 5043,1548 R6_AMP21.1@5043,1571.1
NetC4_AMP21_2: C4_AMP21.2 Q1_AMP21.1 R2_AMP21.1 R3_AMP21.2 | length 672.2
  Top Layer w7: v1@4957,1758.1 R3_AMP21.2@4957,1718.88 4965.78,1718.88 4994.56,1690.1 R2_AMP21.1@5000.22,1690.1 5000.22,1662.88 5010,1653.1 C4_AMP21.2@5010,1598.66 C4_AMP21.2@5010,1597.28 ; v1@5045.34,2130.44 Q1_AMP21.1@5045.34,2191.7
  Bottom Layer w7: v1(4956,1759.1) 4956,1786.1 4940,1802.1 4940,1995.4 5044,2099.4 v1(5044,2129.1)
NetC4_AMP22_1: C4_AMP22.1 Q0_AMP22.3 R6_AMP22.1 | length 127.9
  Top Layer w7: C4_AMP22.1@5192,1571.1 R6_AMP22.1@5225,1571.1 ; R6_AMP22.1@5225,1572.48 R6_AMP22.1@5225,1571.1 ; Q0_AMP22.3@5236,1482.1 5236,1537 5225,1548 R6_AMP22.1@5225,1571.1
NetC4_AMP22_2: C4_AMP22.2 Q1_AMP22.1 R2_AMP22.1 R3_AMP22.2 | length 672.2
  Top Layer w7: v1@5139,1758.1 R3_AMP22.2@5139,1718.88 5147.78,1718.88 5176.56,1690.1 R2_AMP22.1@5182.22,1690.1 5182.22,1662.88 5192,1653.1 C4_AMP22.2@5192,1598.66 C4_AMP22.2@5192,1597.28 ; v1@5227.34,2130.44 Q1_AMP22.1@5227.34,2191.7
  Bottom Layer w7: v1(5138,1759.1) 5138,1786.1 5122,1802.1 5122,1995.4 5226,2099.4 v1(5226,2129.1)
NetC4_AMP23_1: C4_AMP23.1 Q0_AMP23.3 R6_AMP23.1 | length 127.9
  Top Layer w7: C4_AMP23.1@5374,1571.1 R6_AMP23.1@5407,1571.1 ; R6_AMP23.1@5407,1572.48 R6_AMP23.1@5407,1571.1 ; Q0_AMP23.3@5418,1482.1 5418,1537 5407,1548 R6_AMP23.1@5407,1571.1
NetC4_AMP23_2: C4_AMP23.2 Q1_AMP23.1 R2_AMP23.1 R3_AMP23.2 | length 672.2
  Top Layer w7: v1@5321,1758.1 R3_AMP23.2@5321,1718.88 5329.78,1718.88 5358.56,1690.1 R2_AMP23.1@5364.22,1690.1 5364.22,1662.88 5374,1653.1 C4_AMP23.2@5374,1598.66 C4_AMP23.2@5374,1597.28 ; v1@5409.34,2130.44 Q1_AMP23.1@5409.34,2191.7
  Bottom Layer w7: v1(5320,1759.1) 5320,1786.1 5304,1802.1 5304,1995.4 5408,2099.4 v1(5408,2129.1)
NetC4_AMP24_1: C4_AMP24.1 Q0_AMP24.3 R6_AMP24.1 | length 127.9
  Top Layer w7: C4_AMP24.1@5556,1571.1 R6_AMP24.1@5589,1571.1 ; R6_AMP24.1@5589,1572.48 R6_AMP24.1@5589,1571.1 ; Q0_AMP24.3@5600,1482.1 5600,1537 5589,1548 R6_AMP24.1@5589,1571.1
NetC4_AMP24_2: C4_AMP24.2 Q1_AMP24.1 R2_AMP24.1 R3_AMP24.2 | length 672.2
  Top Layer w7: v1@5503,1758.1 R3_AMP24.2@5503,1718.88 5511.78,1718.88 5540.56,1690.1 R2_AMP24.1@5546.22,1690.1 5546.22,1662.88 5556,1653.1 C4_AMP24.2@5556,1598.66 C4_AMP24.2@5556,1597.28 ; v1@5591.34,2130.44 Q1_AMP24.1@5591.34,2191.7
  Bottom Layer w7: v1(5502,1759.1) 5502,1786.1 5486,1802.1 5486,1995.4 5590,2099.4 v1(5590,2129.1)
NetC4_AMP25_1: C4_AMP25.1 Q0_AMP25.3 R6_AMP25.1 | length 127.9
  Top Layer w7: C4_AMP25.1@5738,1571.1 R6_AMP25.1@5771,1571.1 ; R6_AMP25.1@5771,1572.48 R6_AMP25.1@5771,1571.1 ; Q0_AMP25.3@5782,1482.1 5782,1537 5771,1548 R6_AMP25.1@5771,1571.1
NetC4_AMP25_2: C4_AMP25.2 Q1_AMP25.1 R2_AMP25.1 R3_AMP25.2 | length 672.2
  Top Layer w7: v1@5685,1758.1 R3_AMP25.2@5685,1718.88 5693.78,1718.88 5722.56,1690.1 R2_AMP25.1@5728.22,1690.1 5728.22,1662.88 5738,1653.1 C4_AMP25.2@5738,1598.66 C4_AMP25.2@5738,1597.28 ; v1@5773.34,2130.44 Q1_AMP25.1@5773.34,2191.7
  Bottom Layer w7: v1(5684,1759.1) 5684,1786.1 5668,1802.1 5668,1995.4 5772,2099.4 v1(5772,2129.1)
NetC4_AMP26_1: C4_AMP26.1 Q0_AMP26.3 R6_AMP26.1 | length 127.9
  Top Layer w7: C4_AMP26.1@5921,1571.57 R6_AMP26.1@5954,1571.57 ; R6_AMP26.1@5954,1572.95 R6_AMP26.1@5954,1571.57 ; Q0_AMP26.3@5965,1482.57 5965,1537.47 5954,1548.47 R6_AMP26.1@5954,1571.57
NetC4_AMP26_2: C4_AMP26.2 Q1_AMP26.1 R2_AMP26.1 R3_AMP26.2 | length 672.2
  Top Layer w7: v1@5868,1758.57 R3_AMP26.2@5868,1719.35 5876.78,1719.35 5905.56,1690.57 R2_AMP26.1@5911.22,1690.57 5911.22,1663.35 5921,1653.57 C4_AMP26.2@5921,1599.13 C4_AMP26.2@5921,1597.75 ; v1@5956.34,2130.91 Q1_AMP26.1@5956.34,2192.17
  Bottom Layer w7: v1(5867,1759.57) 5867,1786.57 5851,1802.57 5851,1995.86 5955,2099.86 v1(5955,2129.57)
NetC4_AMP27_1: C4_AMP27.1 Q0_AMP27.3 R6_AMP27.1 | length 127.9
  Top Layer w7: C4_AMP27.1@6103,1571.57 R6_AMP27.1@6136,1571.57 ; R6_AMP27.1@6136,1572.95 R6_AMP27.1@6136,1571.57 ; Q0_AMP27.3@6147,1482.57 6147,1537.47 6136,1548.47 R6_AMP27.1@6136,1571.57
NetC4_AMP27_2: C4_AMP27.2 Q1_AMP27.1 R2_AMP27.1 R3_AMP27.2 | length 672.2
  Top Layer w7: v1@6050,1758.57 R3_AMP27.2@6050,1719.35 6058.78,1719.35 6087.56,1690.57 R2_AMP27.1@6093.22,1690.57 6093.22,1663.35 6103,1653.57 C4_AMP27.2@6103,1599.13 C4_AMP27.2@6103,1597.75 ; v1@6138.34,2130.91 Q1_AMP27.1@6138.34,2192.17
  Bottom Layer w7: v1(6049,1759.57) 6049,1786.57 6033,1802.57 6033,1995.86 6137,2099.86 v1(6137,2129.57)
NetC4_AMP28_1: C4_AMP28.1 Q0_AMP28.3 R6_AMP28.1 | length 127.9
  Top Layer w7: C4_AMP28.1@6285,1571.57 R6_AMP28.1@6318,1571.57 ; R6_AMP28.1@6318,1572.95 R6_AMP28.1@6318,1571.57 ; Q0_AMP28.3@6329,1482.57 6329,1537.47 6318,1548.47 R6_AMP28.1@6318,1571.57
NetC4_AMP28_2: C4_AMP28.2 Q1_AMP28.1 R2_AMP28.1 R3_AMP28.2 | length 672.2
  Top Layer w7: v1@6232,1758.57 R3_AMP28.2@6232,1719.35 6240.78,1719.35 6269.56,1690.57 R2_AMP28.1@6275.22,1690.57 6275.22,1663.35 6285,1653.57 C4_AMP28.2@6285,1599.13 C4_AMP28.2@6285,1597.75 ; v1@6320.34,2130.91 Q1_AMP28.1@6320.34,2192.17
  Bottom Layer w7: v1(6231,1759.57) 6231,1786.57 6215,1802.57 6215,1995.86 6319,2099.86 v1(6319,2129.57)
NetC4_AMP29_1: C4_AMP29.1 Q0_AMP29.3 R6_AMP29.1 | length 127.9
  Top Layer w7: C4_AMP29.1@6467,1571.57 R6_AMP29.1@6500,1571.57 ; R6_AMP29.1@6500,1572.95 R6_AMP29.1@6500,1571.57 ; Q0_AMP29.3@6511,1482.57 6511,1537.47 6500,1548.47 R6_AMP29.1@6500,1571.57
NetC4_AMP29_2: C4_AMP29.2 Q1_AMP29.1 R2_AMP29.1 R3_AMP29.2 | length 672.2
  Top Layer w7: v1@6414,1758.57 R3_AMP29.2@6414,1719.35 6422.78,1719.35 6451.56,1690.57 R2_AMP29.1@6457.22,1690.57 6457.22,1663.35 6467,1653.57 C4_AMP29.2@6467,1599.13 C4_AMP29.2@6467,1597.75 ; v1@6502.34,2130.91 Q1_AMP29.1@6502.34,2192.17
  Bottom Layer w7: v1(6413,1759.57) 6413,1786.57 6397,1802.57 6397,1995.86 6501,2099.86 v1(6501,2129.57)
NetC4_AMP30_1: C4_AMP30.1 Q0_AMP30.3 R6_AMP30.1 | length 127.9
  Top Layer w7: C4_AMP30.1@6649,1572 R6_AMP30.1@6682,1572 ; R6_AMP30.1@6682,1573.38 R6_AMP30.1@6682,1572 ; Q0_AMP30.3@6693,1483 6693,1537.9 6682,1548.9 R6_AMP30.1@6682,1572
NetC4_AMP30_2: C4_AMP30.2 Q1_AMP30.1 R2_AMP30.1 R3_AMP30.2 | length 672.2
  Top Layer w7: v1@6596,1759 R3_AMP30.2@6596,1719.78 6604.78,1719.78 6633.56,1691 R2_AMP30.1@6639.22,1691 6639.22,1663.78 6649,1654 C4_AMP30.2@6649,1599.56 C4_AMP30.2@6649,1598.18 ; v1@6684.34,2131.34 Q1_AMP30.1@6684.34,2192.6
  Bottom Layer w7: v1(6595,1760) 6595,1787 6579,1803 6579,1996.29 6683,2100.29 v1(6683,2130)
NetC5_AMP1_1: C5_AMP1.1 Q2_AMP1.2 R5_AMP1.1 | length 111.8
  Top Layer w7: Q2_AMP1.2@1350.59,1839.57 1350.59,1799.45 1366.6,1783.44 C5_AMP1.1@1387,1783.44 ; R5_AMP1.1@1387,1755.6 C5_AMP1.1@1387,1783.44 ; C5_AMP1.1@1387,1784.22 C5_AMP1.1@1387,1783.44
NetC5_AMP2_1: C5_AMP2.1 Q2_AMP2.2 R5_AMP2.1 | length 111.8
  Top Layer w7: Q2_AMP2.2@1533.59,1839.57 1533.59,1799.45 1549.6,1783.44 C5_AMP2.1@1570,1783.44 ; R5_AMP2.1@1570,1755.6 C5_AMP2.1@1570,1783.44 ; C5_AMP2.1@1570,1784.22 C5_AMP2.1@1570,1783.44
NetC5_AMP3_1: C5_AMP3.1 Q2_AMP3.2 R5_AMP3.1 | length 111.8
  Top Layer w7: Q2_AMP3.2@1716.59,1839.57 1716.59,1799.45 1732.6,1783.44 C5_AMP3.1@1753,1783.44 ; R5_AMP3.1@1753,1755.6 C5_AMP3.1@1753,1783.44 ; C5_AMP3.1@1753,1784.22 C5_AMP3.1@1753,1783.44
NetC5_AMP4_1: C5_AMP4.1 Q2_AMP4.2 R5_AMP4.1 | length 111.8
  Top Layer w7: Q2_AMP4.2@1900.59,1839.57 1900.59,1799.45 1916.6,1783.44 C5_AMP4.1@1937,1783.44 ; R5_AMP4.1@1937,1755.6 C5_AMP4.1@1937,1783.44 ; C5_AMP4.1@1937,1784.22 C5_AMP4.1@1937,1783.44
NetC5_AMP5_1: C5_AMP5.1 Q2_AMP5.2 R5_AMP5.1 | length 111.8
  Top Layer w7: Q2_AMP5.2@2083.59,1839.57 2083.59,1799.45 2099.6,1783.44 C5_AMP5.1@2120,1783.44 ; R5_AMP5.1@2120,1755.6 C5_AMP5.1@2120,1783.44 ; C5_AMP5.1@2120,1784.22 C5_AMP5.1@2120,1783.44
NetC5_AMP6_1: C5_AMP6.1 Q2_AMP6.2 R5_AMP6.1 | length 111.8
  Top Layer w7: Q2_AMP6.2@2265.59,1839.57 2265.59,1799.45 2281.6,1783.44 C5_AMP6.1@2302,1783.44 ; R5_AMP6.1@2302,1755.6 C5_AMP6.1@2302,1783.44 ; C5_AMP6.1@2302,1784.22 C5_AMP6.1@2302,1783.44
NetC5_AMP7_1: C5_AMP7.1 Q2_AMP7.2 R5_AMP7.1 | length 111.8
  Top Layer w7: Q2_AMP7.2@2447.59,1839.57 2447.59,1799.45 2463.6,1783.44 C5_AMP7.1@2484,1783.44 ; R5_AMP7.1@2484,1755.6 C5_AMP7.1@2484,1783.44 ; C5_AMP7.1@2484,1784.22 C5_AMP7.1@2484,1783.44
NetC5_AMP8_1: C5_AMP8.1 Q2_AMP8.2 R5_AMP8.1 | length 111.8
  Top Layer w7: Q2_AMP8.2@2628.59,1839.57 2628.59,1799.45 2644.6,1783.44 C5_AMP8.1@2665,1783.44 ; R5_AMP8.1@2665,1755.6 C5_AMP8.1@2665,1783.44 ; C5_AMP8.1@2665,1784.22 C5_AMP8.1@2665,1783.44
NetC5_AMP9_1: C5_AMP9.1 Q2_AMP9.2 R5_AMP9.1 | length 111.8
  Top Layer w7: Q2_AMP9.2@2809.59,1839.57 2809.59,1799.45 2825.6,1783.44 C5_AMP9.1@2846,1783.44 ; R5_AMP9.1@2846,1755.6 C5_AMP9.1@2846,1783.44 ; C5_AMP9.1@2846,1784.22 C5_AMP9.1@2846,1783.44
NetC5_AMP10_1: C5_AMP10.1 Q2_AMP10.2 R5_AMP10.1 | length 111.8
  Top Layer w7: Q2_AMP10.2@2990.59,1839.57 2990.59,1799.45 3006.6,1783.44 C5_AMP10.1@3027,1783.44 ; R5_AMP10.1@3027,1755.6 C5_AMP10.1@3027,1783.44 ; C5_AMP10.1@3027,1784.22 C5_AMP10.1@3027,1783.44
NetC5_AMP11_1: C5_AMP11.1 Q2_AMP11.2 R5_AMP11.1 | length 111.8
  Top Layer w7: Q2_AMP11.2@3173.59,1839.57 3173.59,1799.45 3189.6,1783.44 C5_AMP11.1@3210,1783.44 ; R5_AMP11.1@3210,1755.6 C5_AMP11.1@3210,1783.44 ; C5_AMP11.1@3210,1784.22 C5_AMP11.1@3210,1783.44
NetC5_AMP12_1: C5_AMP12.1 Q2_AMP12.2 R5_AMP12.1 | length 111.8
  Top Layer w7: Q2_AMP12.2@3354.59,1839.57 3354.59,1799.45 3370.6,1783.44 C5_AMP12.1@3391,1783.44 ; R5_AMP12.1@3391,1755.6 C5_AMP12.1@3391,1783.44 ; C5_AMP12.1@3391,1784.22 C5_AMP12.1@3391,1783.44
NetC5_AMP13_1: C5_AMP13.1 Q2_AMP13.2 R5_AMP13.1 | length 111.8
  Top Layer w7: Q2_AMP13.2@3536.59,1839.57 3536.59,1799.45 3552.6,1783.44 C5_AMP13.1@3573,1783.44 ; R5_AMP13.1@3573,1755.6 C5_AMP13.1@3573,1783.44 ; C5_AMP13.1@3573,1784.22 C5_AMP13.1@3573,1783.44
NetC5_AMP14_1: C5_AMP14.1 Q2_AMP14.2 R5_AMP14.1 | length 111.8
  Top Layer w7: Q2_AMP14.2@3718.59,1839.57 3718.59,1799.45 3734.6,1783.44 C5_AMP14.1@3755,1783.44 ; R5_AMP14.1@3755,1755.6 C5_AMP14.1@3755,1783.44 ; C5_AMP14.1@3755,1784.22 C5_AMP14.1@3755,1783.44
NetC5_AMP15_1: C5_AMP15.1 Q2_AMP15.2 R5_AMP15.1 | length 111.8
  Top Layer w7: Q2_AMP15.2@3900.59,1839.57 3900.59,1799.45 3916.6,1783.44 C5_AMP15.1@3937,1783.44 ; R5_AMP15.1@3937,1755.6 C5_AMP15.1@3937,1783.44 ; C5_AMP15.1@3937,1784.22 C5_AMP15.1@3937,1783.44
NetC5_AMP16_1: C5_AMP16.1 Q2_AMP16.2 R5_AMP16.1 | length 111.8
  Top Layer w7: Q2_AMP16.2@4084.59,1839.57 4084.59,1799.45 4100.6,1783.44 C5_AMP16.1@4121,1783.44 ; R5_AMP16.1@4121,1755.6 C5_AMP16.1@4121,1783.44 ; C5_AMP16.1@4121,1784.22 C5_AMP16.1@4121,1783.44
NetC5_AMP17_1: C5_AMP17.1 Q2_AMP17.2 R5_AMP17.1 | length 111.8
  Top Layer w7: Q2_AMP17.2@4267.59,1839.57 4267.59,1799.45 4283.6,1783.44 C5_AMP17.1@4304,1783.44 ; R5_AMP17.1@4304,1755.6 C5_AMP17.1@4304,1783.44 ; C5_AMP17.1@4304,1784.22 C5_AMP17.1@4304,1783.44
NetC5_AMP18_1: C5_AMP18.1 Q2_AMP18.2 R5_AMP18.1 | length 111.8
  Top Layer w7: Q2_AMP18.2@4449.59,1839.57 4449.59,1799.45 4465.6,1783.44 C5_AMP18.1@4486,1783.44 ; R5_AMP18.1@4486,1755.6 C5_AMP18.1@4486,1783.44 ; C5_AMP18.1@4486,1784.22 C5_AMP18.1@4486,1783.44
NetC5_AMP19_1: C5_AMP19.1 Q2_AMP19.2 R5_AMP19.1 | length 111.8
  Top Layer w7: Q2_AMP19.2@4631.59,1839.57 4631.59,1799.45 4647.6,1783.44 C5_AMP19.1@4668,1783.44 ; R5_AMP19.1@4668,1755.6 C5_AMP19.1@4668,1783.44 ; C5_AMP19.1@4668,1784.22 C5_AMP19.1@4668,1783.44
NetC5_AMP20_1: C5_AMP20.1 Q2_AMP20.2 R5_AMP20.1 | length 111.8
  Top Layer w7: Q2_AMP20.2@4814.59,1839.57 4814.59,1799.45 4830.6,1783.44 C5_AMP20.1@4851,1783.44 ; R5_AMP20.1@4851,1755.6 C5_AMP20.1@4851,1783.44 ; C5_AMP20.1@4851,1784.22 C5_AMP20.1@4851,1783.44
NetC5_AMP21_1: C5_AMP21.1 Q2_AMP21.2 R5_AMP21.1 | length 111.8
  Top Layer w7: Q2_AMP21.2@4997.59,1839.67 4997.59,1799.55 5013.6,1783.55 C5_AMP21.1@5034,1783.55 ; R5_AMP21.1@5034,1755.7 C5_AMP21.1@5034,1783.55 ; C5_AMP21.1@5034,1784.32 C5_AMP21.1@5034,1783.55
NetC5_AMP22_1: C5_AMP22.1 Q2_AMP22.2 R5_AMP22.1 | length 111.8
  Top Layer w7: Q2_AMP22.2@5179.59,1839.67 5179.59,1799.55 5195.6,1783.55 C5_AMP22.1@5216,1783.55 ; R5_AMP22.1@5216,1755.7 C5_AMP22.1@5216,1783.55 ; C5_AMP22.1@5216,1784.32 C5_AMP22.1@5216,1783.55
NetC5_AMP23_1: C5_AMP23.1 Q2_AMP23.2 R5_AMP23.1 | length 111.8
  Top Layer w7: Q2_AMP23.2@5361.59,1839.67 5361.59,1799.55 5377.6,1783.55 C5_AMP23.1@5398,1783.55 ; R5_AMP23.1@5398,1755.7 C5_AMP23.1@5398,1783.55 ; C5_AMP23.1@5398,1784.32 C5_AMP23.1@5398,1783.55
NetC5_AMP24_1: C5_AMP24.1 Q2_AMP24.2 R5_AMP24.1 | length 111.8
  Top Layer w7: Q2_AMP24.2@5543.59,1839.67 5543.59,1799.55 5559.6,1783.55 C5_AMP24.1@5580,1783.55 ; R5_AMP24.1@5580,1755.7 C5_AMP24.1@5580,1783.55 ; C5_AMP24.1@5580,1784.32 C5_AMP24.1@5580,1783.55
NetC5_AMP25_1: C5_AMP25.1 Q2_AMP25.2 R5_AMP25.1 | length 111.8
  Top Layer w7: Q2_AMP25.2@5725.59,1839.67 5725.59,1799.55 5741.6,1783.55 C5_AMP25.1@5762,1783.55 ; R5_AMP25.1@5762,1755.7 C5_AMP25.1@5762,1783.55 ; C5_AMP25.1@5762,1784.32 C5_AMP25.1@5762,1783.55
NetC5_AMP26_1: C5_AMP26.1 Q2_AMP26.2 R5_AMP26.1 | length 111.8
  Top Layer w7: Q2_AMP26.2@5908.59,1840.14 5908.59,1800.02 5924.6,1784.01 C5_AMP26.1@5945,1784.01 ; R5_AMP26.1@5945,1756.17 C5_AMP26.1@5945,1784.01 ; C5_AMP26.1@5945,1784.79 C5_AMP26.1@5945,1784.01
NetC5_AMP27_1: C5_AMP27.1 Q2_AMP27.2 R5_AMP27.1 | length 111.8
  Top Layer w7: Q2_AMP27.2@6090.59,1840.14 6090.59,1800.02 6106.6,1784.01 C5_AMP27.1@6127,1784.01 ; R5_AMP27.1@6127,1756.17 C5_AMP27.1@6127,1784.01 ; C5_AMP27.1@6127,1784.79 C5_AMP27.1@6127,1784.01
NetC5_AMP28_1: C5_AMP28.1 Q2_AMP28.2 R5_AMP28.1 | length 111.8
  Top Layer w7: Q2_AMP28.2@6272.59,1840.14 6272.59,1800.02 6288.6,1784.01 C5_AMP28.1@6309,1784.01 ; R5_AMP28.1@6309,1756.17 C5_AMP28.1@6309,1784.01 ; C5_AMP28.1@6309,1784.79 C5_AMP28.1@6309,1784.01
NetC5_AMP29_1: C5_AMP29.1 Q2_AMP29.2 R5_AMP29.1 | length 111.8
  Top Layer w7: Q2_AMP29.2@6454.59,1840.14 6454.59,1800.02 6470.6,1784.01 C5_AMP29.1@6491,1784.01 ; R5_AMP29.1@6491,1756.17 C5_AMP29.1@6491,1784.01 ; C5_AMP29.1@6491,1784.79 C5_AMP29.1@6491,1784.01
NetC5_AMP30_1: C5_AMP30.1 Q2_AMP30.2 R5_AMP30.1 | length 111.8
  Top Layer w7: Q2_AMP30.2@6636.59,1840.57 6636.59,1800.45 6652.6,1784.44 C5_AMP30.1@6673,1784.44 ; R5_AMP30.1@6673,1756.6 C5_AMP30.1@6673,1784.44 ; C5_AMP30.1@6673,1785.22 C5_AMP30.1@6673,1784.44
NetC5_SUMMER1_1: C5_SUMMER1.1 Q5_SUMMER1.3 R13_SUMMER1.1 | length 144.2
  Top Layer w7: C5_SUMMER1.1@1592,2664.6 Q5_SUMMER1.3@1643.26,2664.6 ; R13_SUMMER1.1@1592,2733.22 1609.78,2733.22 1628,2715 1628,2667 Q5_SUMMER1.3@1628,2665.6
NetC5_SUMMER1_2: C5_SUMMER1.2 Q6_SUMMER1.1 RC_SUMMER1.2 RD_SUMMER1.1 | length 144.2
  Top Layer w7: Q6_SUMMER1.1@1505.8,2723.22 RD_SUMMER1.1@1557,2723.22 ; RC_SUMMER1.2@1557,2665.78 1557,2690 ; RD_SUMMER1.1@1557,2724.6 RD_SUMMER1.1@1557,2723.22 ; C5_SUMMER1.2@1591.22,2690 1557,2690 ; 1557,2690 RD_SUMMER1.1@1557,2723.22
NetC5_SUMMER2_1: C5_SUMMER2.1 Q5_SUMMER2.3 R13_SUMMER2.1 | length 144.2
  Top Layer w7: C5_SUMMER2.1@2507,2664.6 Q5_SUMMER2.3@2558.26,2664.6 ; R13_SUMMER2.1@2507,2733.22 2524.78,2733.22 2543,2715 2543,2667 Q5_SUMMER2.3@2543,2665.6
NetC5_SUMMER2_2: C5_SUMMER2.2 Q6_SUMMER2.1 RC_SUMMER2.2 RD_SUMMER2.1 | length 144.2
  Top Layer w7: Q6_SUMMER2.1@2420.8,2723.22 RD_SUMMER2.1@2472,2723.22 ; RC_SUMMER2.2@2472,2665.78 2472,2690 ; RD_SUMMER2.1@2472,2724.6 RD_SUMMER2.1@2472,2723.22 ; C5_SUMMER2.2@2506.22,2690 2472,2690 ; 2472,2690 RD_SUMMER2.1@2472,2723.22
NetC5_SUMMER3_1: C5_SUMMER3.1 Q5_SUMMER3.3 R13_SUMMER3.1 | length 144.2
  Top Layer w7: C5_SUMMER3.1@3415,2664.6 Q5_SUMMER3.3@3466.26,2664.6 ; R13_SUMMER3.1@3415,2733.22 3432.78,2733.22 3451,2715 3451,2667 Q5_SUMMER3.3@3451,2665.6
NetC5_SUMMER3_2: C5_SUMMER3.2 Q6_SUMMER3.1 RC_SUMMER3.2 RD_SUMMER3.1 | length 144.2
  Top Layer w7: Q6_SUMMER3.1@3328.8,2723.22 RD_SUMMER3.1@3380,2723.22 ; RC_SUMMER3.2@3380,2665.78 3380,2690 ; RD_SUMMER3.1@3380,2724.6 RD_SUMMER3.1@3380,2723.22 ; C5_SUMMER3.2@3414.22,2690 3380,2690 ; 3380,2690 RD_SUMMER3.1@3380,2723.22
NetC5_SUMMER4_1: C5_SUMMER4.1 Q5_SUMMER4.3 R13_SUMMER4.1 | length 144.2
  Top Layer w7: C5_SUMMER4.1@4326,2664.6 Q5_SUMMER4.3@4377.26,2664.6 ; R13_SUMMER4.1@4326,2733.22 4343.78,2733.22 4362,2715 4362,2667 Q5_SUMMER4.3@4362,2665.6
NetC5_SUMMER4_2: C5_SUMMER4.2 Q6_SUMMER4.1 RC_SUMMER4.2 RD_SUMMER4.1 | length 144.2
  Top Layer w7: Q6_SUMMER4.1@4239.8,2723.22 RD_SUMMER4.1@4291,2723.22 ; RC_SUMMER4.2@4291,2665.78 4291,2690 ; RD_SUMMER4.1@4291,2724.6 RD_SUMMER4.1@4291,2723.22 ; C5_SUMMER4.2@4325.22,2690 4291,2690 ; 4291,2690 RD_SUMMER4.1@4291,2723.22
NetC5_SUMMER5_1: C5_SUMMER5.1 Q5_SUMMER5.3 R13_SUMMER5.1 | length 144.2
  Top Layer w7: C5_SUMMER5.1@5239,2664.7 Q5_SUMMER5.3@5290.26,2664.7 ; R13_SUMMER5.1@5239,2733.32 5256.78,2733.32 5275,2715.1 5275,2667.1 Q5_SUMMER5.3@5275,2665.7
NetC5_SUMMER5_2: C5_SUMMER5.2 Q6_SUMMER5.1 RC_SUMMER5.2 RD_SUMMER5.1 | length 144.2
  Top Layer w7: Q6_SUMMER5.1@5152.8,2723.32 RD_SUMMER5.1@5204,2723.32 ; RC_SUMMER5.2@5204,2665.88 5204,2690.1 ; RD_SUMMER5.1@5204,2724.7 RD_SUMMER5.1@5204,2723.32 ; C5_SUMMER5.2@5238.22,2690.1 5204,2690.1 ; 5204,2690.1 RD_SUMMER5.1@5204,2723.32
NetC5_SUMMER6_1: C5_SUMMER6.1 Q5_SUMMER6.3 R13_SUMMER6.1 | length 144.2
  Top Layer w7: C5_SUMMER6.1@6150,2665.17 Q5_SUMMER6.3@6201.26,2665.17 ; R13_SUMMER6.1@6150,2733.79 6167.78,2733.79 6186,2715.57 6186,2667.57 Q5_SUMMER6.3@6186,2666.17
NetC5_SUMMER6_2: C5_SUMMER6.2 Q6_SUMMER6.1 RC_SUMMER6.2 RD_SUMMER6.1 | length 144.2
  Top Layer w7: Q6_SUMMER6.1@6063.8,2723.79 RD_SUMMER6.1@6115,2723.79 ; RC_SUMMER6.2@6115,2666.35 6115,2690.57 ; RD_SUMMER6.1@6115,2725.17 RD_SUMMER6.1@6115,2723.79 ; C5_SUMMER6.2@6149.22,2690.57 6115,2690.57 ; 6115,2690.57 RD_SUMMER6.1@6115,2723.79
NetC6_AMP1_1: C6_AMP1.1 Q3_AMP1.2 R8_AMP1.1 | length 177.2
  Top Layer w7: Q3_AMP1.2@1372.59,1984.57 1394.68,1984.57 1437,1942.24 1437,1912.94 1432,1907.94 C6_AMP1.1@1432,1885.78 1432,1882.78 1421.59,1882.78 1412.59,1873.78 R8_AMP1.1@1402,1873.78
NetC6_AMP1_2: C6_AMP1.2 R7_AMP1.1 | length 42.4
  Top Layer w7: R7_AMP1.1@1432,1812.78 C6_AMP1.2@1432,1855.22
NetC6_AMP2_1: C6_AMP2.1 Q3_AMP2.2 R8_AMP2.1 | length 177.2
  Top Layer w7: Q3_AMP2.2@1555.59,1984.57 1577.68,1984.57 1620,1942.24 1620,1912.94 1615,1907.94 C6_AMP2.1@1615,1885.78 1615,1882.78 1604.59,1882.78 1595.59,1873.78 R8_AMP2.1@1585,1873.78
NetC6_AMP2_2: C6_AMP2.2 R7_AMP2.1 | length 42.4
  Top Layer w7: R7_AMP2.1@1615,1812.78 C6_AMP2.2@1615,1855.22
NetC6_AMP3_1: C6_AMP3.1 Q3_AMP3.2 R8_AMP3.1 | length 177.2
  Top Layer w7: Q3_AMP3.2@1738.59,1984.57 1760.68,1984.57 1803,1942.24 1803,1912.94 1798,1907.94 C6_AMP3.1@1798,1885.78 1798,1882.78 1787.59,1882.78 1778.59,1873.78 R8_AMP3.1@1768,1873.78
NetC6_AMP3_2: C6_AMP3.2 R7_AMP3.1 | length 42.4
  Top Layer w7: R7_AMP3.1@1798,1812.78 C6_AMP3.2@1798,1855.22
NetC6_AMP4_1: C6_AMP4.1 Q3_AMP4.2 R8_AMP4.1 | length 177.2
  Top Layer w7: Q3_AMP4.2@1922.59,1984.57 1944.68,1984.57 1987,1942.24 1987,1912.94 1982,1907.94 C6_AMP4.1@1982,1885.78 1982,1882.78 1971.59,1882.78 1962.59,1873.78 R8_AMP4.1@1952,1873.78
NetC6_AMP4_2: C6_AMP4.2 R7_AMP4.1 | length 42.4
  Top Layer w7: R7_AMP4.1@1982,1812.78 C6_AMP4.2@1982,1855.22
NetC6_AMP5_1: C6_AMP5.1 Q3_AMP5.2 R8_AMP5.1 | length 177.2
  Top Layer w7: Q3_AMP5.2@2105.59,1984.57 2127.68,1984.57 2170,1942.24 2170,1912.94 2165,1907.94 C6_AMP5.1@2165,1885.78 2165,1882.78 2154.59,1882.78 2145.59,1873.78 R8_AMP5.1@2135,1873.78
NetC6_AMP5_2: C6_AMP5.2 R7_AMP5.1 | length 42.4
  Top Layer w7: R7_AMP5.1@2165,1812.78 C6_AMP5.2@2165,1855.22
NetC6_AMP6_1: C6_AMP6.1 Q3_AMP6.2 R8_AMP6.1 | length 177.2
  Top Layer w7: Q3_AMP6.2@2287.59,1984.57 2309.68,1984.57 2352,1942.24 2352,1912.94 2347,1907.94 C6_AMP6.1@2347,1885.78 2347,1882.78 2336.59,1882.78 2327.59,1873.78 R8_AMP6.1@2317,1873.78
NetC6_AMP6_2: C6_AMP6.2 R7_AMP6.1 | length 42.4
  Top Layer w7: R7_AMP6.1@2347,1812.78 C6_AMP6.2@2347,1855.22
NetC6_AMP7_1: C6_AMP7.1 Q3_AMP7.2 R8_AMP7.1 | length 177.2
  Top Layer w7: Q3_AMP7.2@2469.59,1984.57 2491.68,1984.57 2534,1942.24 2534,1912.94 2529,1907.94 C6_AMP7.1@2529,1885.78 2529,1882.78 2518.59,1882.78 2509.59,1873.78 R8_AMP7.1@2499,1873.78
